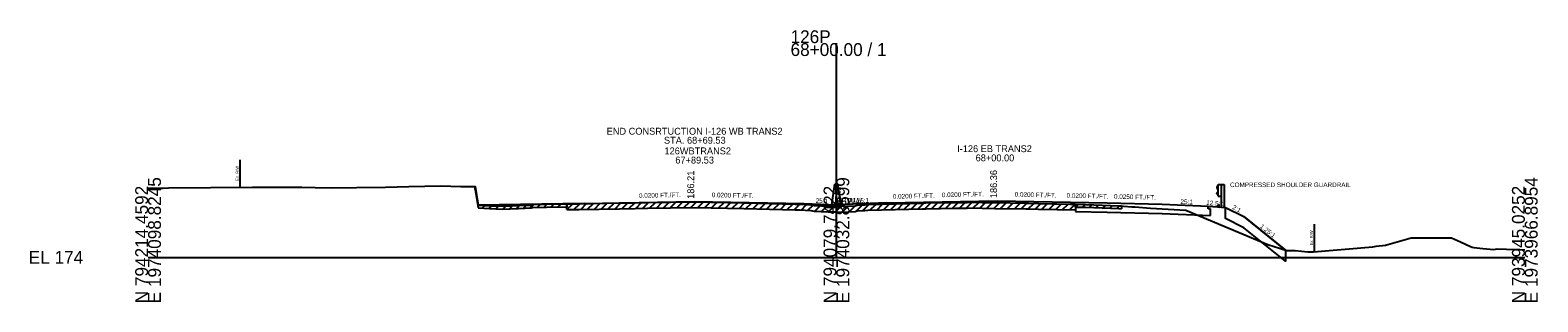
# Model space of a CAD drawing. Extents: x -161 to 1970889, y -4362 to 797231.
# Drawn here: x 2974.3 to 3302.8, y 2490.3 to 2549.5 of the extents above; entities that cross this region are included whole.
import ezdxf

# ---------------------------------------------------------------- set-up
doc = ezdxf.new("R2010")
doc.units = 0
for name, color, linetype in [('Default', 7, 'Continuous'), ('RD_GPK_XS_Cell', 7, 'Continuous'), ('RD_XS_Base', 7, 'Continuous'), ('RD_XS_CurbTop', 7, 'Continuous'), ('RD_XS_EarthShd', 7, 'Continuous'), ('RD_XS_ExGround', 7, 'Continuous'), ('RD_XS_ExPaveRet', 7, 'Continuous'), ('RD_XS_ExRW', 7, 'Continuous'), ('RD_XS_GR', 7, 'Continuous'), ('RD_XS_MedBWall', 7, 'Continuous'), ('RD_XS_Misc_Line', 7, 'Continuous'), ('RD_XS_Pave', 7, 'Continuous'), ('RD_XS_PaveOvlay', 7, 'Continuous'), ('RD_XS_PaveShd', 7, 'Continuous'), ('RD_XS_TieSlope', 7, 'Continuous'), ('RD_XS_TX_Elev_EX', 7, 'Continuous'), ('RD_XS_TX_Elev_PR', 7, 'Continuous'), ('RD_XS_TX_MkPT', 7, 'Continuous'), ('RD_XS_TX_Notes', 7, 'Continuous'), ('RD_XS_TX_Profile', 7, 'Continuous'), ('RD_XS_TX_ShdSlope', 7, 'Continuous'), ('RD_XS_TX_Slope', 7, 'Continuous'), ('RD_XS_TX_Station', 7, 'Continuous')]:
    doc.layers.add(name, color=color, linetype=linetype)

msp = doc.modelspace()

# ---------------------------------------------------------------- linework, layer by layer
at = {"layer": 'RD_GPK_XS_Cell'}
for p, q in [((3150, 2500), (3150, 2546.7)), ((3000, 2500), (3150, 2500)), ((3150, 2500), (3300, 2500))]:
    msp.add_line(p, q, dxfattribs=at)
at = {"layer": 'RD_XS_Base'}
for p, q in [((3231, 2510.62), (3231, 2511.18)), ((3231.5, 2510.6), (3231, 2510.62)), ((3231.5, 2509.12), (3231.5, 2510.6)), ((3202.09, 2509.97), (3209, 2509.84)), ((3209, 2509.84), (3221, 2509.54)), ((3221, 2509.54), (3231.5, 2509.12))]:
    msp.add_line(p, q, dxfattribs=at)
at = {"layer": 'RD_XS_CurbTop'}
for p, q in [((3233, 2511.02), (3233.25, 2511.47)), ((3233, 2511.02), (3233.47, 2510.98)), ((3233.47, 2510.98), (3233.41, 2511.42))]:
    msp.add_line(p, q, dxfattribs=at)
msp.add_ellipse((3233.32, 2511.39), major_axis=(0, -0.131), ratio=0.686, start_param=1.762783, end_param=4.036677, dxfattribs=at)
at = {"layer": 'RD_XS_EarthShd'}
msp.add_line((3231, 2511.18), (3233, 2511.02), dxfattribs=at)
at = {"layer": 'RD_XS_ExGround'}
msp.add_lwpolyline([(3000, 2515.08), (3003.27, 2515.12), (3004.47, 2515.18), (3022.73, 2515.3), (3025.52, 2515.31), (3028.2, 2515.34), (3033.5, 2515.31), (3036.39, 2515.27), (3039.88, 2515.14), (3045.42, 2515.27), (3051.71, 2515.29), (3056.81, 2515.42), (3063.76, 2515.57), (3068.18, 2515.47), (3070.26, 2515.44), (3071.28, 2515.45), (3071.91, 2511.4), (3074.42, 2511.25), (3077.14, 2511.13), (3080.75, 2511.3), (3083.58, 2511.41), (3083.84, 2511.51), (3086.83, 2511.57), (3093.97, 2511.71), (3102.7, 2511.87), (3106.14, 2511.92), (3108.84, 2511.97), (3113.86, 2512.06), (3118.06, 2512.14), (3122.71, 2512.05), (3129.83, 2511.9), (3140.99, 2511.62), (3141.99, 2511.59), (3144.39, 2511.48), (3145.18, 2511.34), (3148.2, 2511.17), (3148.55, 2511.17), (3150, 2511.15), (3151.14, 2511.14), (3154.08, 2511.23), (3154.52, 2511.42), (3156.19, 2511.49), (3156.87, 2511.52), (3168.72, 2511.85), (3169.16, 2511.86), (3169.49, 2511.86), (3175.92, 2511.96), (3178.52, 2512), (3180.1, 2512.02), (3181.79, 2511.99), (3184.54, 2511.94), (3191.27, 2511.82), (3191.82, 2511.81), (3194.01, 2511.76), (3204.26, 2511.55), (3211.52, 2511.26), (3212.09, 2511.24), (3212.58, 2511.15), (3214.34, 2511.03), (3215.01, 2510.99), (3218.46, 2510.76), (3226.11, 2510.26), (3244.03, 2502.82), (3248.16, 2501.48), (3249.99, 2501.51), (3252.71, 2501.2), (3253.34, 2501.19), (3253.98, 2501.22), (3266.9, 2502.33), (3267.64, 2502.42), (3269.64, 2502.68), (3273.2, 2503.69), (3275.22, 2504.29), (3277.72, 2504.29), (3284.06, 2504.29), (3285.96, 2503.39), (3288.19, 2502.35), (3288.51, 2502.21), (3288.92, 2502.15), (3290.88, 2501.97), (3293.22, 2501.75), (3293.63, 2501.82), (3293.94, 2501.87), (3300, 2501.67)], dxfattribs=at)
at = {"layer": 'RD_XS_ExPaveRet'}
for p, q in [((3071.28, 2514.82), (3071.28, 2515.45)), ((3071.28, 2514.82), (3071.91, 2510.77)), ((3071.91, 2510.77), (3074.42, 2510.63)), ((3074.42, 2510.63), (3077.14, 2510.51)), ((3077.14, 2510.51), (3080.75, 2510.68)), ((3080.75, 2510.68), (3083.58, 2510.78)), ((3083.58, 2510.78), (3083.84, 2510.89)), ((3083.84, 2510.89), (3086.83, 2510.95)), ((3086.83, 2510.95), (3091.28, 2511.03)), ((3091.28, 2510.41), (3091.28, 2511.66)), ((3091.28, 2511.66), (3091.28, 2511.03)), ((3091.28, 2510.41), (3093.97, 2510.46)), ((3093.97, 2510.46), (3102.7, 2510.62)), ((3102.7, 2510.62), (3106.14, 2510.67)), ((3106.14, 2510.67), (3108.84, 2510.72)), ((3108.84, 2510.72), (3113.86, 2510.81)), ((3113.86, 2510.81), (3118.06, 2510.89)), ((3118.06, 2510.89), (3122.71, 2510.8)), ((3122.71, 2510.8), (3129.83, 2510.65)), ((3129.83, 2510.65), (3140.99, 2510.37)), ((3140.99, 2510.37), (3141.99, 2510.34)), ((3141.99, 2510.34), (3144.39, 2510.23)), ((3144.39, 2510.23), (3145.18, 2510.09)), ((3145.18, 2510.09), (3148.2, 2509.92)), ((3154.08, 2509.98), (3154.52, 2510.17)), ((3154.52, 2510.17), (3156.19, 2510.24)), ((3156.19, 2510.24), (3156.87, 2510.27)), ((3156.87, 2510.27), (3168.72, 2510.6)), ((3168.72, 2510.6), (3169.16, 2510.61)), ((3169.16, 2510.61), (3169.49, 2510.61)), ((3169.49, 2510.61), (3175.92, 2510.71)), ((3175.92, 2510.71), (3178.52, 2510.75)), ((3178.52, 2510.75), (3180.1, 2510.77)), ((3180.1, 2510.77), (3181.79, 2510.74)), ((3181.79, 2510.74), (3184.54, 2510.69)), ((3184.54, 2510.69), (3191.27, 2510.57)), ((3191.27, 2510.57), (3191.82, 2510.56)), ((3191.82, 2510.56), (3194.01, 2510.51)), ((3194.01, 2510.51), (3202.09, 2510.35)), ((3202.09, 2511.6), (3202.09, 2510.35)), ((3202.09, 2510.97), (3202.09, 2511.6)), ((3202.09, 2510.97), (3204.26, 2510.93)), ((3204.26, 2510.93), (3211.52, 2510.64)), ((3211.52, 2510.64), (3212.09, 2510.61)), ((3212.09, 2511.24), (3212.09, 2510.61)), ((3148.2, 2509.92), (3148.55, 2509.92)), ((3148.55, 2509.92), (3150, 2509.9)), ((3150, 2509.9), (3151.14, 2509.89)), ((3151.14, 2509.89), (3154.08, 2509.98))]:
    msp.add_line(p, q, dxfattribs=at)
at = {"layer": 'RD_XS_ExRW'}
for p, q in [((3020, 2521.28), (3020, 2515.28)), ((3254.09, 2507.23), (3254.09, 2501.23))]:
    msp.add_line(p, q, dxfattribs=at)
at = {"layer": 'RD_XS_GR'}
for p, q in [((3233.15, 2515.73), (3232.87, 2515.29)), ((3232.87, 2515.29), (3232.87, 2515.18)), ((3232.87, 2515.18), (3233.15, 2514.74)), ((3232.87, 2514.03), (3233.15, 2514.47)), ((3232.87, 2513.92), (3232.87, 2514.03)), ((3233.15, 2513.48), (3232.87, 2513.92)), ((3233.15, 2515.89), (3233.81, 2515.89)), ((3233.15, 2513.32), (3233.15, 2515.89)), ((3233.15, 2513.32), (3233.81, 2513.32)), ((3233.81, 2515.89), (3234.48, 2515.89)), ((3233.81, 2515.89), (3233.81, 2510.95)), ((3234.48, 2515.89), (3234.48, 2510.84))]:
    msp.add_line(p, q, dxfattribs=at)
at = {"layer": 'RD_XS_MedBWall'}
for p, q in [((3149, 2511.47), (3149.67, 2515.95)), ((3150.33, 2515.95), (3149.67, 2515.95)), ((3150.33, 2515.94), (3150.33, 2515.95)), ((3151, 2511.46), (3150.33, 2515.94))]:
    msp.add_line(p, q, dxfattribs=at)
at = {"layer": 'RD_XS_Misc_Line'}
for p, q in [((3071.28, 2514.82), (3071.37, 2514.91)), ((3072.78, 2510.72), (3073.37, 2511.31)), ((3074.28, 2510.64), (3074.88, 2511.23)), ((3075.78, 2510.57), (3076.38, 2511.17)), ((3077.28, 2510.51), (3077.94, 2511.17)), ((3078.78, 2510.59), (3079.44, 2511.24)), ((3080.28, 2510.66), (3080.94, 2511.31)), ((3081.78, 2510.72), (3082.43, 2511.37)), ((3083.28, 2510.77), (3084.03, 2511.52)), ((3084.78, 2510.91), (3085.42, 2511.54)), ((3086.28, 2510.94), (3086.92, 2511.58)), ((3087.78, 2510.97), (3088.42, 2511.6)), ((3089.28, 2511), (3089.92, 2511.63)), ((3091.28, 2510.41), (3092.56, 2511.68)), ((3092.78, 2510.44), (3094.06, 2511.71)), ((3094.28, 2510.47), (3095.55, 2511.74)), ((3095.78, 2510.49), (3097.05, 2511.77)), ((3097.28, 2510.52), (3098.55, 2511.79)), ((3098.78, 2510.55), (3100.05, 2511.82)), ((3100.28, 2510.57), (3101.55, 2511.85)), ((3101.78, 2510.6), (3103.05, 2511.87)), ((3103.28, 2510.63), (3104.55, 2511.9)), ((3104.78, 2510.65), (3106.05, 2511.92)), ((3106.28, 2510.68), (3107.55, 2511.95)), ((3107.78, 2510.7), (3109.05, 2511.98)), ((3109.28, 2510.73), (3110.55, 2512)), ((3110.78, 2510.76), (3112.05, 2512.03)), ((3112.28, 2510.78), (3113.55, 2512.06)), ((3113.78, 2510.81), (3115.06, 2512.09)), ((3115.28, 2510.84), (3116.56, 2512.11)), ((3116.78, 2510.87), (3118.06, 2512.14)), ((3118.28, 2510.89), (3119.51, 2512.11)), ((3119.78, 2510.86), (3121.01, 2512.08)), ((3121.28, 2510.83), (3122.51, 2512.05)), ((3122.78, 2510.8), (3124.01, 2512.02)), ((3124.28, 2510.77), (3125.51, 2511.99)), ((3125.78, 2510.73), (3127.01, 2511.96)), ((3127.28, 2510.7), (3128.51, 2511.92)), ((3128.78, 2510.67), (3130, 2511.89)), ((3130.28, 2510.64), (3131.5, 2511.85)), ((3131.78, 2510.6), (3133, 2511.82)), ((3133.28, 2510.56), (3134.5, 2511.78)), ((3134.78, 2510.52), (3136, 2511.74)), ((3136.28, 2510.48), (3137.5, 2511.7)), ((3137.78, 2510.45), (3139, 2511.67)), ((3139.28, 2510.41), (3140.5, 2511.63)), ((3140.78, 2510.37), (3142, 2511.59)), ((3142.28, 2510.33), (3143.47, 2511.52)), ((3143.78, 2510.26), (3144.91, 2511.39)), ((3145.28, 2510.08), (3146.46, 2511.27)), ((3146.78, 2510), (3147.96, 2511.18)), ((3148.28, 2509.92), (3149.52, 2511.15)), ((3149.78, 2509.9), (3151.02, 2511.14)), ((3151.28, 2509.89), (3152.57, 2511.18)), ((3152.78, 2509.94), (3154.07, 2511.23)), ((3154.28, 2510.07), (3155.68, 2511.47)), ((3155.78, 2510.23), (3157.08, 2511.52)), ((3157.28, 2510.28), (3158.57, 2511.56)), ((3158.78, 2510.32), (3160.07, 2511.61)), ((3160.28, 2510.36), (3161.57, 2511.65)), ((3161.78, 2510.4), (3163.07, 2511.69)), ((3163.28, 2510.45), (3164.57, 2511.73)), ((3164.78, 2510.49), (3166.07, 2511.77)), ((3166.28, 2510.53), (3167.57, 2511.81)), ((3167.78, 2510.57), (3169.07, 2511.85)), ((3169.28, 2510.61), (3170.55, 2511.88)), ((3170.78, 2510.63), (3172.05, 2511.9)), ((3172.28, 2510.65), (3173.55, 2511.92)), ((3173.78, 2510.67), (3175.05, 2511.94)), ((3175.28, 2510.7), (3176.55, 2511.97)), ((3176.78, 2510.72), (3178.05, 2511.99)), ((3178.28, 2510.74), (3179.55, 2512.01)), ((3179.78, 2510.77), (3181.02, 2512)), ((3181.28, 2510.75), (3182.51, 2511.97)), ((3182.78, 2510.72), (3184.01, 2511.95)), ((3184.28, 2510.69), (3185.51, 2511.92)), ((3185.78, 2510.67), (3187.01, 2511.89)), ((3187.28, 2510.64), (3188.51, 2511.87)), ((3188.78, 2510.61), (3190.01, 2511.84)), ((3190.28, 2510.58), (3191.51, 2511.81)), ((3191.78, 2510.56), (3193.01, 2511.78)), ((3193.28, 2510.53), (3194.51, 2511.75)), ((3194.78, 2510.5), (3196.01, 2511.72)), ((3196.28, 2510.47), (3197.51, 2511.69)), ((3197.78, 2510.44), (3199.01, 2511.66)), ((3199.28, 2510.41), (3200.51, 2511.63)), ((3200.78, 2510.37), (3202.01, 2511.6)), ((3202.09, 2510.97), (3202.71, 2511.59)), ((3203.59, 2510.94), (3204.21, 2511.56)), ((3205.09, 2510.9), (3205.69, 2511.5)), ((3206.59, 2510.84), (3207.19, 2511.44)), ((3208.09, 2510.77), (3208.69, 2511.38)), ((3209.59, 2510.71), (3210.19, 2511.32)), ((3211.09, 2510.65), (3211.69, 2511.26))]:
    msp.add_line(p, q, dxfattribs=at)
at = {"layer": 'RD_XS_Pave'}
for p, q in [((3095, 2511.73), (3119, 2512.21)), ((3119, 2512.21), (3143, 2511.73)), ((3161, 2511.88), (3185, 2512.36)), ((3185, 2512.36), (3209, 2511.88)), ((3209, 2511.88), (3221, 2511.58))]:
    msp.add_line(p, q, dxfattribs=at)
at = {"layer": 'RD_XS_PaveOvlay'}
for p, q in [((3150, 2511.15), (3151.14, 2511.14)), ((3151.14, 2511.14), (3154.08, 2511.23)), ((3154.08, 2511.23), (3154.52, 2511.42)), ((3154.52, 2511.42), (3156.19, 2511.49)), ((3156.19, 2511.49), (3156.87, 2511.52)), ((3156.87, 2511.52), (3168.72, 2511.85)), ((3168.72, 2511.85), (3169.16, 2511.86)), ((3169.16, 2511.86), (3169.49, 2511.86)), ((3169.49, 2511.86), (3175.92, 2511.96)), ((3175.92, 2511.96), (3178.52, 2512)), ((3178.52, 2512), (3180.1, 2512.02)), ((3180.1, 2512.02), (3181.79, 2511.99)), ((3181.79, 2511.99), (3184.54, 2511.94)), ((3184.54, 2511.94), (3191.27, 2511.82)), ((3191.27, 2511.82), (3191.82, 2511.81)), ((3191.82, 2511.81), (3194.01, 2511.76)), ((3194.01, 2511.76), (3202.09, 2511.6)), ((3202.09, 2511.6), (3202.09, 2509.97))]:
    msp.add_line(p, q, dxfattribs=at)
at = {"layer": 'RD_XS_PaveShd'}
for p, q in [((3095, 2511.73), (3071.91, 2511.4)), ((3143, 2511.73), (3150, 2511.45)), ((3161, 2511.88), (3150, 2511.44)), ((3221, 2511.58), (3231, 2511.18))]:
    msp.add_line(p, q, dxfattribs=at)
at = {"layer": 'RD_XS_TieSlope'}
for p, q in [((3233, 2511.02), (3234.75, 2510.88)), ((3234.75, 2510.88), (3238.75, 2508.88)), ((3247.88, 2501.57), (3238.75, 2508.88))]:
    msp.add_line(p, q, dxfattribs=at)
msp.add_lwpolyline([(3234.75, 2510.88), (3238.75, 2508.88), (3247.88, 2501.57), (3247.88, 2499.17), (3238.75, 2506.47), (3234.75, 2508.47)], close=True, dxfattribs=at)
at = {"layer": 'RD_XS_TX_Slope'}
msp.add_line((3225, 2500), (3225, 2500), dxfattribs=at)

# ---------------------------------------------------------------- texts
at = {"layer": 'Default'}
for p in [(3150, 2511.45), (3150, 2511.37)]:
    msp.add_text('35', height=1.5, dxfattribs=at).set_placement(p)
at = {"layer": 'RD_GPK_XS_Cell'}
for s, p in [('126P', (3140, 2546.7)), ('68+00.00 / 1', (3140, 2543.9)), ('EL 174', (2974, 2498.6))]:
    msp.add_text(s, height=2.8, dxfattribs=at).set_placement(p)
for s, p in [('E 1974098.8245', (3002.8, 2490)), ('E 1974032.8599', (3152.8, 2490)), ('E 1973966.8954', (3302.8, 2490)), ('N 794214.4592', (3000, 2490)), ('N 794079.7422', (3150, 2490)), ('N 793945.0252', (3300, 2490))]:
    msp.add_text(s, height=2.8, rotation=90, dxfattribs=at).set_placement(p)
at = {"layer": 'RD_XS_ExRW'}
for p in [(3019.75, 2516.67), (3253.84, 2502.61)]:
    msp.add_text('Ex. R/W ', height=0.65, rotation=90, dxfattribs=at).set_placement(p)
at = {"layer": 'RD_XS_TX_Elev_EX'}
msp.add_text('185.15', height=1, rotation=90, dxfattribs=at).set_placement((3151, 2511.15))
at = {"layer": 'RD_XS_TX_Elev_PR'}
for s, p in [(' 186.21', (3119, 2512.21)), (' 186.36', (3185, 2512.36))]:
    msp.add_text(s, height=1.5, rotation=90, dxfattribs=at).set_placement(p)
at = {"layer": 'RD_XS_TX_MkPT'}
for s, p in [('WBW', (3149, 2511.47)), ('EBW', (3151, 2511.46))]:
    msp.add_text(s, height=1.5, dxfattribs=at).set_placement(p)
at = {"layer": 'RD_XS_TX_Notes'}
for s, p in [('END CONSRTUCTION I-126 WB TRANS2', (3099.93, 2526.75)), ('STA. 68+69.53', (3112.42, 2524.78))]:
    msp.add_text(s, height=1.5, dxfattribs=at).set_placement(p)
at = {"layer": 'RD_XS_TX_Profile'}
for rotation, p in [(357.7094, (3145.46, 2511.88)), (2.2906, (3154.44, 2511.86)), (357.7097, (3224.95, 2511.67))]:
    msp.add_text('25:1', height=1, rotation=rotation, dxfattribs=at).set_placement(p)
at = {"layer": 'RD_XS_TX_ShdSlope'}
msp.add_text('12.5:1', height=1, rotation=355.4267, dxfattribs=at).set_placement((3230.54, 2511.46))
at = {"layer": 'RD_XS_TX_Slope'}
for s, rotation, p in [('0.0200 FT./FT.', 1.1458, (3106.98, 2512.97)), ('0.0200 FT./FT.', 358.8542, (3122.83, 2513.13)), ('0.0200 FT./FT.', 1.1458, (3162.3, 2512.79)), ('0.0200 FT./FT.', 1.1458, (3172.98, 2513.12)), ('0.0200 FT./FT.', 358.5681, (3188.83, 2513.26)), ('0.0200 FT./FT.', 358.5681, (3200.15, 2513.03)), ('0.0250 FT./FT.', 358.569, (3210.47, 2512.8)), ('2:1', 333.4349, (3236.15, 2510.59)), ('1.25:1', 322.4314, (3242.17, 2506.56))]:
    msp.add_text(s, height=1, rotation=rotation, dxfattribs=at).set_placement(p)
msp.add_text('COMPRESSED SHOULDER GUARDRAIL', height=1, dxfattribs=at).set_placement((3235.76, 2515.32))
at = {"layer": 'RD_XS_TX_Station'}
for s, p in [('126WBTRANS2', (3112.53, 2522.46)), ('I-126 EB TRANS2', (3176.31, 2522.94)), ('67+89.53', (3114.89, 2520.46)), ('68+00.00', (3180.33, 2520.94))]:
    msp.add_text(s, height=1.5, dxfattribs=at).set_placement(p)

doc.saveas('drawing.dxf')
